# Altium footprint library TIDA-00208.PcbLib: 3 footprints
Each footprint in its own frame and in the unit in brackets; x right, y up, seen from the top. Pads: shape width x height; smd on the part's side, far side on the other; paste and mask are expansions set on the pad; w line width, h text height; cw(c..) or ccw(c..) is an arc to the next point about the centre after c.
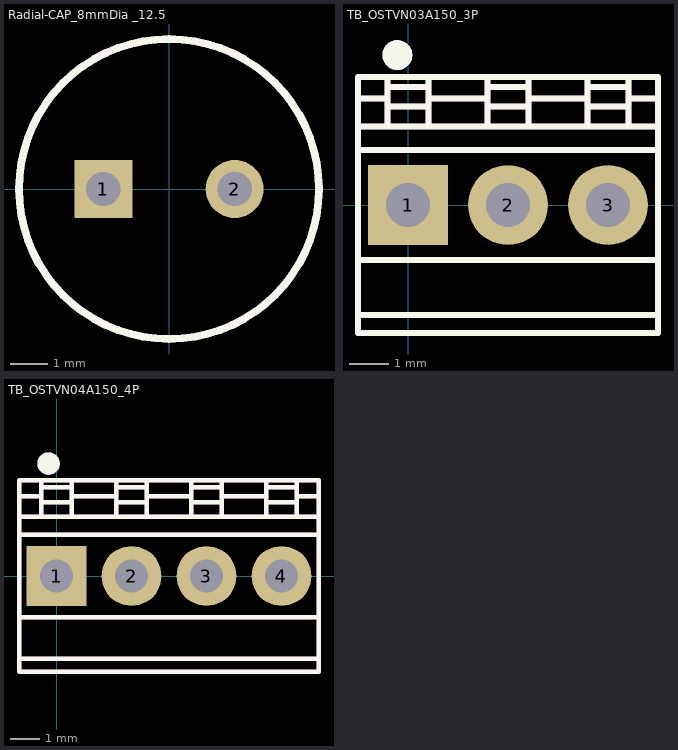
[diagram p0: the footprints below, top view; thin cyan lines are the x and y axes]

## Radial-CAP_8mmDia _12.5 [mil] "Radial, Can"
height 492.13
pads (2):
  rect 61x61 hole 36: 1(-68.9,0)
  round 61 hole 36: 2(68.9,0)
Top Overlay:
  circle w8: c0,0 r157.48
Mechanical 5:
  circle w7.87: c0,0 r157.48
  text ".Designator" at -185,75 h40
3D body: height 492.13, standoff 0, extent -156.23,-157.16 157.49,157.17

## TB_OSTVN03A150_3P [mil]
height 400
pads (3):
  rect 80x80 / inner round 80 / far side rect 80x80 hole 44: 1(0,0)
  round 80 hole 44: 2(100,0) 3(200,0)
Top Overlay:
  circle w10: c-10.63,149.95 r10
  circle w10: c-10.63,149.95 r5
  lines w6: -50,-110.24 250,-110.24 ; -50,-55.12 250,-55.12 ; -50,55.12 250,55.12 ; -50,78.74 250,78.74 ; -50,106.3 -20.87,106.3 ; -20.47,78.74 -20.47,127.95 ; -20.47,98.43 18.5,98.43 ; -20.47,118.11 18.5,118.11 ; 20.47,78.74 20.47,127.95 ; 22.44,106.3 77.56,106.3 ; 79.53,78.74 79.53,127.95 ; 81.5,98.43 116.93,98.43 ; 81.5,118.11 116.93,118.11 ; 120.47,78.74 120.47,127.95 ; 120.87,106.3 179.53,106.3 ; 179.53,78.74 179.53,127.95 ; 181.5,98.43 220.47,98.43 ; 181.5,118.11 220.47,118.11 ; 220.47,78.74 220.47,127.95 ; 220.87,106.3 250,106.3 ; -50,-127.95 250,-127.95 250,127.95 -50,127.95 -50,-127.95
Mechanical 5:
  circle w10: c-10.63,149.95 r5
  circle w10: c-10.63,149.95 r10
  lines w6: -50,-110.24 250,-110.24 ; -50,-55.12 250,-55.12 ; -50,55.12 250,55.12 ; -50,78.74 250,78.74 ; -50,106.3 -20.87,106.3 ; -20.47,78.74 -20.47,127.95 ; -20.47,98.43 18.5,98.43 ; -20.47,118.11 18.5,118.11 ; 20.47,78.74 20.47,127.95 ; 22.44,106.3 77.56,106.3 ; 79.53,78.74 79.53,127.95 ; 81.5,98.43 116.93,98.43 ; 81.5,118.11 116.93,118.11 ; 120.47,78.74 120.47,127.95 ; 120.87,106.3 179.53,106.3 ; 179.53,78.74 179.53,127.95 ; 181.5,98.43 220.47,98.43 ; 181.5,118.11 220.47,118.11 ; 220.47,78.74 220.47,127.95 ; 220.87,106.3 250,106.3 ; -50,-127.95 -50,127.95 250,127.95 250,-127.95 -50,-127.95
  text ".Designator" at 30,145 h40

## TB_OSTVN04A150_4P [mil]
height 400
pads (4):
  rect 80x80 / inner round 80 / far side rect 80x80 hole 44: 1(0,0)
  round 80 hole 44: 2(100,0) 3(200,0) 4(300,0)
Top Overlay:
  circle w10: c-10.63,149.95 r10
  circle w10: c-10.63,149.95 r5
  lines w6: -50,-110.24 350,-110.24 ; -50,-55.12 350,-55.12 ; -50,55.12 350,55.12 ; -50,78.74 350,78.74 ; -50,106.3 -20.87,106.3 ; -20.47,78.74 -20.47,127.95 ; -20.47,98.43 18.5,98.43 ; -20.47,118.11 18.5,118.11 ; 20.47,78.74 20.47,127.95 ; 22.44,106.3 77.56,106.3 ; 79.53,78.74 79.53,127.95 ; 81.5,98.43 116.93,98.43 ; 81.5,118.11 116.93,118.11 ; 120.47,78.74 120.47,127.95 ; 120.87,106.3 179.53,106.3 ; 179.53,78.74 179.53,127.95 ; 181.5,98.43 220.47,98.43 ; 181.5,118.11 220.47,118.11 ; 220.87,106.3 279.53,106.3 ; 279.53,78.74 279.53,127.95 ; 281.5,98.43 320.47,98.43 ; 281.5,118.11 320.47,118.11 ; 320.47,78.74 320.47,127.95 ; 320.87,106.3 350,106.3 ; -50,-127.95 350,-127.95 350,127.95 -50,127.95 -50,-127.95 ; 220.47,78.74 220.47,127.95 220.47,78.74
Mechanical 5:
  circle w10: c-10.63,149.95 r5
  circle w10: c-10.63,149.95 r10
  lines w6: -50,-110.24 350,-110.24 ; -50,-55.12 350,-55.12 ; -50,55.12 350,55.12 ; -50,78.74 350,78.74 ; -50,106.3 -20.87,106.3 ; -20.47,78.74 -20.47,127.95 ; -20.47,98.43 18.5,98.43 ; -20.47,118.11 18.5,118.11 ; 20.47,78.74 20.47,127.95 ; 22.44,106.3 77.56,106.3 ; 79.53,78.74 79.53,127.95 ; 81.5,98.43 116.93,98.43 ; 81.5,118.11 116.93,118.11 ; 120.47,78.74 120.47,127.95 ; 120.87,106.3 179.53,106.3 ; 179.53,78.74 179.53,127.95 ; 181.5,98.43 220.47,98.43 ; 181.5,118.11 220.47,118.11 ; 220.87,106.3 279.53,106.3 ; 279.53,78.74 279.53,127.95 ; 281.5,98.43 320.47,98.43 ; 281.5,118.11 320.47,118.11 ; 320.47,78.74 320.47,127.95 ; 320.87,106.3 350,106.3 ; 350,-127.95 350,127.95 ; 350,-127.95 350,127.95 ; 350,-127.95 -50,-127.95 -50,127.95 350,127.95 ; 220.47,78.74 220.47,127.95 220.47,78.74
  text ".Designator" at 35,180 h40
